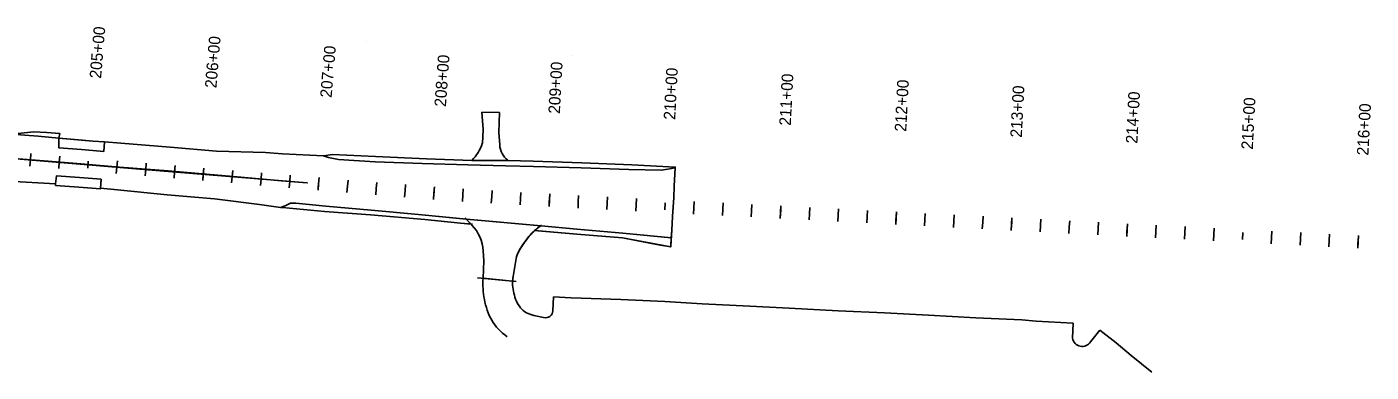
# Model space of a CAD drawing. Extents: x 20499880 to 20505309, y 7953507 to 7955507.
# Drawn here: x 20504147 to 20505309, y 7953507 to 7953806 of the extents above; entities that cross this region are included whole.
import ezdxf

# ---------------------------------------------------------------- set-up
doc = ezdxf.new("R2010")
doc.units = 0
for name, color, linetype in [('Alignment', 7, 'Continuous'), ('Curb', 7, 'Continuous'), ('Draft_0', 7, 'Continuous'), ('Entrance', 7, 'Continuous'), ('PavementMarking', 7, 'Continuous')]:
    doc.layers.add(name, color=color, linetype=linetype)

msp = doc.modelspace()

# ---------------------------------------------------------------- linework, layer by layer
at = {"layer": 'Alignment'}
for p, q in [((20504199.9, 7953689.7), (20504199.4, 7953683.6)), ((20504199.9, 7953689.7), (20504199.4, 7953683.6)), ((20504299.3, 7953678.3), (20504299.8, 7953683.7)), ((20504299.3, 7953678.3), (20504298.9, 7953672.9)), ((20504399, 7953670), (20504398.5, 7953664.5)), ((20504399, 7953670), (20504399.4, 7953675.4)), ((20504498.7, 7953662.1), (20504498.3, 7953656.6)), ((20504498.7, 7953662.1), (20504499.1, 7953667.5)), ((20504598.5, 7953655.8), (20504598.8, 7953661.3)), ((20504598.5, 7953655.8), (20504598.2, 7953650.4)), ((20504698.5, 7953653.7), (20504698.2, 7953647.6)), ((20504698.5, 7953653.7), (20504698.2, 7953647.6)), ((20504798.2, 7953645.5), (20504797.9, 7953640.1)), ((20504798.2, 7953645.5), (20504798.5, 7953651)), ((20504898.1, 7953640.4), (20504898.4, 7953645.8)), ((20504898.1, 7953640.4), (20504897.8, 7953634.9)), ((20504997.9, 7953635.2), (20504997.7, 7953629.8)), ((20504997.9, 7953635.2), (20504998.2, 7953640.7)), ((20505097.8, 7953630.1), (20505098.1, 7953635.5)), ((20505097.8, 7953630.1), (20505097.5, 7953624.6)), ((20505197.8, 7953628), (20505197.5, 7953621.9)), ((20505197.8, 7953628), (20505197.5, 7953621.9)), ((20505297.6, 7953619.8), (20505297.8, 7953625.2)), ((20505297.6, 7953619.8), (20505297.3, 7953614.3))]:
    msp.add_line(p, q, dxfattribs=at)
at = {"layer": 'Curb'}
for p, q in [((20504555.2, 7953731.9), (20504540.2, 7953732.2)), ((20504540.2, 7953732.2), (20504541.3, 7953717.2)), ((20504554.9, 7953714.5), (20504555.2, 7953731.9)), ((20504541.3, 7953717.2), (20504540.5, 7953705.1)), ((20504555.5, 7953703.7), (20504554.9, 7953714.5)), ((20504531.3, 7953690.3), (20504562.5, 7953690.4)), ((20504525.7, 7953640.5), (20504531.5, 7953634.4)), ((20504541.3, 7953612.1), (20504541.7, 7953603.3)), ((20504541.7, 7953603.3), (20504541.1, 7953588.4)), ((20504567.1, 7953589.7), (20504569.8, 7953605.3)), ((20504536.2, 7953588.8), (20504569.6, 7953585.6)), ((20504601.9, 7953572.3), (20504601.4, 7953560.2)), ((20504617.2, 7953571.4), (20504601.9, 7953572.3)), ((20504660.1, 7953569.9), (20504617.2, 7953571.4)), ((20504698.2, 7953568.3), (20504660.1, 7953569.9)), ((20504730.4, 7953566.3), (20504698.2, 7953568.3)), ((20504771.7, 7953564.2), (20504730.4, 7953566.3)), ((20504805.8, 7953562.5), (20504771.7, 7953564.2)), ((20504593.5, 7953554.4), (20504584.9, 7953556.2)), ((20504848, 7953560.2), (20504805.8, 7953562.5)), ((20504888, 7953558.3), (20504848, 7953560.2)), ((20504926.3, 7953556.4), (20504888, 7953558.3)), ((20504967.2, 7953554.1), (20504926.3, 7953556.4)), ((20505006.9, 7953552.3), (20504967.2, 7953554.1)), ((20505019.1, 7953551.3), (20505006.9, 7953552.3)), ((20505051.3, 7953549.3), (20505019.1, 7953551.3)), ((20505050.7, 7953536.5), (20505051.3, 7953549.3)), ((20505074.4, 7953543.4), (20505066.2, 7953533.3)), ((20505088.4, 7953532.3), (20505074.4, 7953543.4)), ((20505101.4, 7953521.5), (20505088.4, 7953532.3)), ((20505119.2, 7953507), (20505101.4, 7953521.5))]:
    msp.add_line(p, q, dxfattribs=at)
for points in [[(20504174.4, 7953709.6), (20504156.6, 7953711.2), (20504133.6, 7953713.2)], [(20504707.3, 7953683.9), (20504700.9, 7953682.9), (20504695.2, 7953681.8), (20504667.1, 7953682.5), (20504625.9, 7953683.8), (20504584.7, 7953685.1), (20504560.9, 7953685.6), (20504527.9, 7953686.5), (20504488.6, 7953687.6), (20504447.9, 7953689.2), (20504416.3, 7953691), (20504407.6, 7953693), (20504403.1, 7953694.2), (20504367.7, 7953696.1), (20504353, 7953697.3), (20504310.7, 7953698.4), (20504270.7, 7953701.8), (20504228, 7953705.3), (20504213.8, 7953706.4)], [(20504403.1, 7953694.2), (20504411, 7953695.5), (20504448.2, 7953693.6), (20504492.2, 7953691.7), (20504531.3, 7953690.3)], [(20504707.3, 7953683.9), (20504707.2, 7953684.6), (20504669.7, 7953686.5), (20504626.4, 7953688.2), (20504584.3, 7953689.7), (20504562.5, 7953690.4)], [(20504707.3, 7953683.9), (20504706.4, 7953668.1), (20504705.9, 7953658.1), (20504704.8, 7953641.7), (20504704.2, 7953630), (20504703.4, 7953616.4)], [(20504171.6, 7953670), (20504130.8, 7953672.4)], [(20504526.7, 7953639.5), (20504485.4, 7953643.4), (20504444.3, 7953647.3), (20504405.1, 7953650.8), (20504379.3, 7953653.3), (20504374.6, 7953653.4), (20504370.1, 7953651.1), (20504366, 7953649.7), (20504347.9, 7953652.3), (20504308.9, 7953657.1), (20504268.2, 7953660.6), (20504225, 7953664.9), (20504210.5, 7953666.3)], [(20504366, 7953649.7), (20504367.7, 7953649.5), (20504404.1, 7953646.2), (20504443.8, 7953643.3), (20504490.8, 7953639.2), (20504521.5, 7953635.9), (20504532, 7953635)], [(20504704.1, 7953623.3), (20504662, 7953627.3), (20504622.2, 7953630.7), (20504591.3, 7953633.6), (20504526.7, 7953639.5)], [(20504703.4, 7953616.4), (20504703.3, 7953615.4), (20504692.9, 7953617.3), (20504661.6, 7953623.2), (20504622.3, 7953626.4), (20504585.4, 7953629.7)]]:
    msp.add_lwpolyline(points, dxfattribs=at)
for points in [[(20504213.8, 7953706.4), (20504213.3, 7953698.1), (20504193.9, 7953699.7), (20504174.3, 7953701.3), (20504174.4, 7953709.6), (20504194.8, 7953707.8), (20504203.7, 7953707.1)], [(20504191.6, 7953667.3), (20504210.4, 7953665.6), (20504211, 7953674.1), (20504192.4, 7953675.6), (20504172.4, 7953677), (20504171.6, 7953670), (20504171.6, 7953668.7), (20504191.6, 7953667.3), (20504191.6, 7953667.3)]]:
    msp.add_lwpolyline(points, close=True, dxfattribs=at)
for centre, major_axis, ratio, start_param, end_param in [((20504507.5, 7953715.1), (20.7, 29.5), 0.952447, 4.526801, 5.014331), ((20504574.7, 7953705.3), (11.2, -16), 0.983254, 4.190588, 4.979259), ((20504507.5, 7953610.5), (-6.3, 33.2), 0.999282, 4.569478, 5.308631), ((20504595.4, 7953560.1), (4.82, 3.52), 0.99915, 3.759733, 5.665045), ((20505059, 7953537.7), (3.31, -7.76), 0.999988, 4.455675, 6.906522)]:
    msp.add_ellipse(centre, major_axis=major_axis, ratio=ratio, start_param=start_param, end_param=end_param, dxfattribs=at)
for points in [[(20504569.8, 7953605.3), (20504570.5, 7953609.7), (20504575.5, 7953617.6), (20504582.6, 7953627.2), (20504588.5, 7953631.9), (20504591.7, 7953634.2)], [(20504541.1, 7953588.4), (20504540.8, 7953582.2), (20504541.4, 7953569.9), (20504547.5, 7953551.1), (20504556.3, 7953541.8), (20504561.9, 7953537.7)], [(20504584.9, 7953556.2), (20504580.4, 7953557.1), (20504572.5, 7953561.5), (20504567, 7953575.4), (20504566.3, 7953584.7), (20504567.1, 7953589.7)]]:
    msp.add_open_spline(points, degree=3, dxfattribs=at)
at = {"layer": 'Draft_0'}
msp.add_line((20504569.8, 7953605.3), (20504567.1, 7953589.7), dxfattribs=at)
for points in [[(20503679, 7953730.1), (20504248, 7953682.6), (20504389.1, 7953670.8), (20504366.8, 7953672.8), (20504331.7, 7953675.8), (20504269, 7953681.4), (20504227, 7953684.5), (20504193.5, 7953687.4), (20504172.5, 7953689.1), (20504132.3, 7953692.3)], [(20504133.6, 7953713.2), (20504152.7, 7953715), (20504152.7, 7953715), (20504164.1, 7953714.5), (20504175.3, 7953713.6), (20504174.4, 7953709.6), (20504174.3, 7953701.3), (20504193.9, 7953699.7), (20504213.3, 7953698.1), (20504213.8, 7953706.4), (20504228, 7953705.3), (20504270.7, 7953701.8), (20504310.7, 7953698.4), (20504353, 7953697.3), (20504367.7, 7953696.1), (20504403.1, 7953694.2), (20504407.6, 7953693), (20504416.3, 7953691), (20504447.9, 7953689.2), (20504488.6, 7953687.6), (20504527.9, 7953686.5), (20504560.9, 7953685.6), (20504584.7, 7953685.1), (20504625.9, 7953683.8), (20504667.1, 7953682.5), (20504695.2, 7953681.8), (20504700.9, 7953682.9), (20504707.3, 7953683.9), (20504706.4, 7953668.1), (20504705.9, 7953658.1), (20504704.8, 7953641.7), (20504704.2, 7953630), (20504703.8, 7953623.3), (20504662, 7953627.3), (20504622.2, 7953630.7), (20504591.3, 7953633.6), (20504526.7, 7953639.5), (20504485.4, 7953643.4), (20504444.3, 7953647.3), (20504405.1, 7953650.8), (20504379.3, 7953653.3), (20504374.6, 7953653.4), (20504370.1, 7953651.1), (20504366, 7953649.7), (20504347.9, 7953652.3), (20504308.9, 7953657.1), (20504268.2, 7953660.6), (20504225, 7953664.9), (20504210.5, 7953666.3), (20504211, 7953674.1), (20504192.4, 7953675.6), (20504172.4, 7953677), (20504171.6, 7953670), (20504130.8, 7953672.4)], [(20504531.5, 7953634.4), (20504526.6, 7953639.5), (20504526.7, 7953639.5), (20504591, 7953633.7)], [(20504591, 7953633.7), (20504591.3, 7953633.6), (20504622.2, 7953630.7), (20504662, 7953627.3), (20504703.8, 7953623.3), (20504703.4, 7953616.4), (20504703.3, 7953615.4), (20504661.6, 7953623.2), (20504622.3, 7953626.4), (20504585.8, 7953629.6)], [(20504566.7, 7953585.9), (20504541.1, 7953588.4), (20504541.7, 7953603.3), (20504541.3, 7953612.1)]]:
    msp.add_lwpolyline(points, dxfattribs=at)
for points in [[(20504174.4, 7953709.6), (20504203.7, 7953707.1), (20504213.8, 7953706.4), (20504213.3, 7953698.1), (20504193.9, 7953699.7), (20504174.3, 7953701.3)], [(20504416.3, 7953691), (20504407.6, 7953693), (20504403.1, 7953694.2), (20504411, 7953695.5), (20504448.2, 7953693.6), (20504492.2, 7953691.7), (20504531.3, 7953690.3), (20504562.5, 7953690.4), (20504584.3, 7953689.7), (20504626.4, 7953688.2), (20504669.7, 7953686.5), (20504707.2, 7953684.6), (20504707.3, 7953683.9), (20504700.9, 7953682.9), (20504695.2, 7953681.8), (20504667.1, 7953682.5), (20504625.9, 7953683.8), (20504584.7, 7953685.1), (20504560.9, 7953685.6), (20504527.9, 7953686.5), (20504488.6, 7953687.6), (20504447.9, 7953689.2)], [(20504211, 7953674.1), (20504210.4, 7953665.6), (20504191.6, 7953667.3), (20504171.6, 7953668.7), (20504171.6, 7953670), (20504172.4, 7953677), (20504192.4, 7953675.6)], [(20504490.8, 7953639.2), (20504443.8, 7953643.3), (20504404.1, 7953646.2), (20504367.7, 7953649.5), (20504366, 7953649.7), (20504370.1, 7953651.1), (20504374.6, 7953653.4), (20504379.3, 7953653.3), (20504405.1, 7953650.8), (20504444.3, 7953647.3), (20504485.4, 7953643.4), (20504526.6, 7953639.5), (20504530.8, 7953635.1), (20504521.5, 7953635.9)]]:
    msp.add_lwpolyline(points, close=True, dxfattribs=at)
msp.add_ellipse((20504507.5, 7953610.5), major_axis=(-6.3, 33.2), ratio=0.999282, start_param=4.569478, end_param=5.308631, dxfattribs=at)
for points, degree in [([(20504591, 7953633.7), (20504588.1, 7953631.6), (20504586.1, 7953630), (20504584.2, 7953628.2)], 2), ([(20504589.4, 7953632.5), (20504589.9, 7953632.9), (20504590.4, 7953633.3), (20504591, 7953633.7)], 2), ([(20504584.2, 7953628.2), (20504580.9, 7953624.9), (20504575.5, 7953617.6), (20504570.5, 7953609.7), (20504569.8, 7953605.3)], 3), ([(20504585.8, 7953629.6), (20504585.9, 7953629.7), (20504586.1, 7953629.8), (20504586.2, 7953630)], 2), ([(20504586.2, 7953630), (20504586.4, 7953630.2), (20504586.6, 7953630.3), (20504586.9, 7953630.5)], 2), ([(20504586.9, 7953630.5), (20504586.9, 7953630.6), (20504587, 7953630.6), (20504587.1, 7953630.7)], 2), ([(20504587.1, 7953630.7), (20504587.1, 7953630.7), (20504587.1, 7953630.8), (20504587.2, 7953630.8)], 2), ([(20504587.2, 7953630.8), (20504587.2, 7953630.8), (20504587.2, 7953630.8), (20504587.3, 7953630.9)], 2), ([(20504587.3, 7953630.9), (20504587.5, 7953631), (20504587.6, 7953631.1), (20504587.8, 7953631.3)], 2), ([(20504587.3, 7953630.9), (20504587.3, 7953630.9), (20504587.3, 7953630.9), (20504587.3, 7953630.9)], 2), ([(20504587.3, 7953630.9), (20504587.3, 7953630.9), (20504587.3, 7953630.9), (20504587.3, 7953630.9)], 2), ([(20504587.8, 7953631.3), (20504587.8, 7953631.3), (20504587.9, 7953631.3), (20504587.9, 7953631.4)], 2), ([(20504587.9, 7953631.4), (20504587.9, 7953631.4), (20504588, 7953631.4), (20504588, 7953631.4)], 2), ([(20504588, 7953631.4), (20504588.1, 7953631.5), (20504588.2, 7953631.6), (20504588.3, 7953631.7)], 2), ([(20504588.3, 7953631.7), (20504588.6, 7953631.9), (20504589, 7953632.2), (20504589.4, 7953632.5)], 2), ([(20504567.1, 7953589.7), (20504566.9, 7953588.4), (20504566.8, 7953587.1), (20504566.7, 7953585.9)], 2)]:
    msp.add_open_spline(points, degree=degree, dxfattribs=at)
at = {"layer": 'Entrance'}
for p, q in [((20504149.9, 7953690.8), (20504150.3, 7953696.2)), ((20504174.8, 7953688.7), (20504175.2, 7953694.1)), ((20504149.9, 7953690.8), (20504149.4, 7953685.3)), ((20504174.8, 7953688.7), (20504174.3, 7953683.2)), ((20504199.9, 7953689.7), (20504199.4, 7953683.6)), ((20504199.9, 7953689.7), (20504199.4, 7953683.6)), ((20504224.6, 7953684.5), (20504224.1, 7953679.1)), ((20504224.6, 7953684.5), (20504225, 7953690)), ((20504249.5, 7953682.5), (20504249.1, 7953677)), ((20504249.5, 7953682.5), (20504250, 7953687.9)), ((20504274.4, 7953680.4), (20504274, 7953674.9)), ((20504274.4, 7953680.4), (20504274.9, 7953685.8)), ((20504299.6, 7953681.3), (20504299.1, 7953675.2)), ((20504299.6, 7953681.3), (20504299.1, 7953675.2)), ((20504324.2, 7953676.2), (20504324.7, 7953681.7)), ((20504324.2, 7953676.2), (20504323.8, 7953670.8)), ((20504349.2, 7953674.1), (20504348.7, 7953668.7)), ((20504349.2, 7953674.1), (20504349.6, 7953679.6)), ((20504374.1, 7953672.1), (20504373.6, 7953666.6)), ((20504374.1, 7953672.1), (20504374.5, 7953677.5)), ((20504399.2, 7953673), (20504398.7, 7953666.9)), ((20504399.2, 7953673), (20504398.7, 7953666.9)), ((20504423.9, 7953667.9), (20504424.4, 7953673.3)), ((20504448.8, 7953665.9), (20504449.3, 7953671.3)), ((20504473.7, 7953663.9), (20504474.2, 7953669.4)), ((20504423.9, 7953667.9), (20504423.4, 7953662.5)), ((20504448.8, 7953665.9), (20504448.4, 7953660.4)), ((20504473.7, 7953663.9), (20504473.3, 7953658.5)), ((20504498.9, 7953665.1), (20504498.5, 7953659)), ((20504498.9, 7953665.1), (20504498.5, 7953659)), ((20504523.6, 7953660.4), (20504523.3, 7953654.9)), ((20504523.6, 7953660.4), (20504524, 7953665.8)), ((20504548.6, 7953658.7), (20504548.2, 7953653.3)), ((20504548.6, 7953658.7), (20504548.9, 7953664.2)), ((20504573.5, 7953657.2), (20504573.2, 7953651.8)), ((20504573.5, 7953657.2), (20504573.8, 7953662.7)), ((20504598.6, 7953658.9), (20504598.3, 7953652.8)), ((20504598.6, 7953658.9), (20504598.3, 7953652.8)), ((20504623.4, 7953654.5), (20504623.7, 7953660)), ((20504648.4, 7953653.3), (20504648.7, 7953658.7)), ((20504673.4, 7953652), (20504673.7, 7953657.4)), ((20504623.4, 7953654.5), (20504623.2, 7953649.1)), ((20504648.4, 7953653.3), (20504648.1, 7953647.8)), ((20504673.4, 7953652), (20504673.1, 7953646.5)), ((20504698.5, 7953653.7), (20504698.2, 7953647.6)), ((20504698.5, 7953653.7), (20504698.2, 7953647.6)), ((20504723.3, 7953649.4), (20504723, 7953643.9)), ((20504723.3, 7953649.4), (20504723.6, 7953654.8)), ((20504748.3, 7953648.1), (20504748, 7953642.7)), ((20504748.3, 7953648.1), (20504748.6, 7953653.6)), ((20504773.2, 7953646.8), (20504773, 7953641.4)), ((20504773.2, 7953646.8), (20504773.5, 7953652.3)), ((20504798.4, 7953648.6), (20504798.1, 7953642.5)), ((20504798.4, 7953648.6), (20504798.1, 7953642.5)), ((20504823.2, 7953644.2), (20504823.5, 7953649.7)), ((20504848.1, 7953643), (20504848.4, 7953648.4)), ((20504873.1, 7953641.7), (20504873.4, 7953647.1)), ((20504823.2, 7953644.2), (20504822.9, 7953638.8)), ((20504848.1, 7953643), (20504847.9, 7953637.5)), ((20504873.1, 7953641.7), (20504872.8, 7953636.2)), ((20504898.2, 7953643.4), (20504897.9, 7953637.3)), ((20504898.2, 7953643.4), (20504897.9, 7953637.3)), ((20504923, 7953639.1), (20504922.8, 7953633.6)), ((20504923, 7953639.1), (20504923.3, 7953644.5)), ((20504948, 7953637.8), (20504947.7, 7953632.4)), ((20504948, 7953637.8), (20504948.3, 7953643.3)), ((20504973, 7953636.5), (20504972.7, 7953631.1)), ((20504973, 7953636.5), (20504973.3, 7953642)), ((20504998.1, 7953638.3), (20504997.8, 7953632.2)), ((20504998.1, 7953638.3), (20504997.8, 7953632.2)), ((20505022.9, 7953633.9), (20505022.6, 7953628.5)), ((20505022.9, 7953633.9), (20505023.2, 7953639.4)), ((20505047.9, 7953632.7), (20505048.2, 7953638.1)), ((20505072.8, 7953631.4), (20505073.1, 7953636.8)), ((20505122.8, 7953628.8), (20505123.1, 7953634.3)), ((20505047.9, 7953632.7), (20505047.6, 7953627.2)), ((20505072.8, 7953631.4), (20505072.6, 7953625.9)), ((20505098, 7953633.1), (20505097.7, 7953627)), ((20505098, 7953633.1), (20505097.7, 7953627)), ((20505122.8, 7953628.8), (20505122.5, 7953623.3)), ((20505147.7, 7953627.5), (20505147.5, 7953622.1)), ((20505147.7, 7953627.5), (20505148, 7953633)), ((20505172.7, 7953626.2), (20505172.4, 7953620.8)), ((20505172.7, 7953626.2), (20505173, 7953631.7)), ((20505197.8, 7953628), (20505197.5, 7953621.9)), ((20505197.8, 7953628), (20505197.5, 7953621.9)), ((20505222.6, 7953623.7), (20505222.4, 7953618.2)), ((20505222.6, 7953623.7), (20505222.9, 7953629.1)), ((20505247.6, 7953622.4), (20505247.3, 7953616.9)), ((20505247.6, 7953622.4), (20505247.9, 7953627.8)), ((20505272.6, 7953621.1), (20505272.9, 7953626.5)), ((20505297.7, 7953622.8), (20505297.4, 7953616.7)), ((20505297.7, 7953622.8), (20505297.4, 7953616.7)), ((20505272.6, 7953621.1), (20505272.3, 7953615.6))]:
    msp.add_line(p, q, dxfattribs=at)
at = {"layer": 'PavementMarking'}
for p, q in [((20504440.1, 7953793), (20504440.1, 7953793)), ((20504440.1, 7953793), (20504440.1, 7953793)), ((20504617.5, 7953781), (20504617.5, 7953781)), ((20504617.5, 7953781), (20504617.5, 7953781))]:
    msp.add_line(p, q, dxfattribs=at)

# ---------------------------------------------------------------- texts
at = {"layer": 'Alignment'}
for s, rotation, p in [('205+00', 85.2296, (20504210.9, 7953760.9)), ('210+00', 87.0487, (20504707.2, 7953725.3)), ('215+00', 87.0487, (20505206.5, 7953699.6))]:
    msp.add_text(s, height=10.02, rotation=rotation, dxfattribs=at).set_placement(p)
at = {"layer": 'Entrance'}
for s, rotation, p in [('205+00', 85.2296, (20504210.9, 7953760.9)), ('206+00', 85.2308, (20504310.6, 7953752.6)), ('207+00', 85.2308, (20504410.2, 7953744.3)), ('208+00', 85.9236, (20504509, 7953736.5)), ('209+00', 86.9235, (20504607.5, 7953730.5)), ('210+00', 87.0487, (20504707.2, 7953725.3)), ('211+00', 87.0487, (20504807.1, 7953720.2)), ('212+00', 87.0487, (20504906.9, 7953715)), ('213+00', 87.0487, (20505006.8, 7953709.9)), ('214+00', 87.0487, (20505106.7, 7953704.7)), ('215+00', 87.0487, (20505206.5, 7953699.6)), ('216+00', 87.0487, (20505306.4, 7953694.4))]:
    msp.add_text(s, height=10.02, rotation=rotation, dxfattribs=at).set_placement(p)

doc.saveas('drawing.dxf')
